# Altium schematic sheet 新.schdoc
size 254 x 209 mm; Symbol: Drawing-Symbol_A4; Company: 嘉立创EDA; Version: V1.0; Page Size: A5; @Project Name: 蜂鸟无人机; @Update Date: 2026-08-29; @Create Date: 2026-08-29; Device: Drawing-Symbol_A4; @Board Name: Board1; @Page Name: P1; @Create Time: 19:18:57; @Page Count: 1; @Page No: 1; @Schematic Name: Schematic1; @Update Time: 19:18:57; @Assembly Variant: Basic; Border: 1; Title Block Position: 3; Size: A4; Width: 1000; Height: 825; Region Start: 1; X Region Count: 6; Y Region Count: 4; Blade Width: 10; Title Block: 1
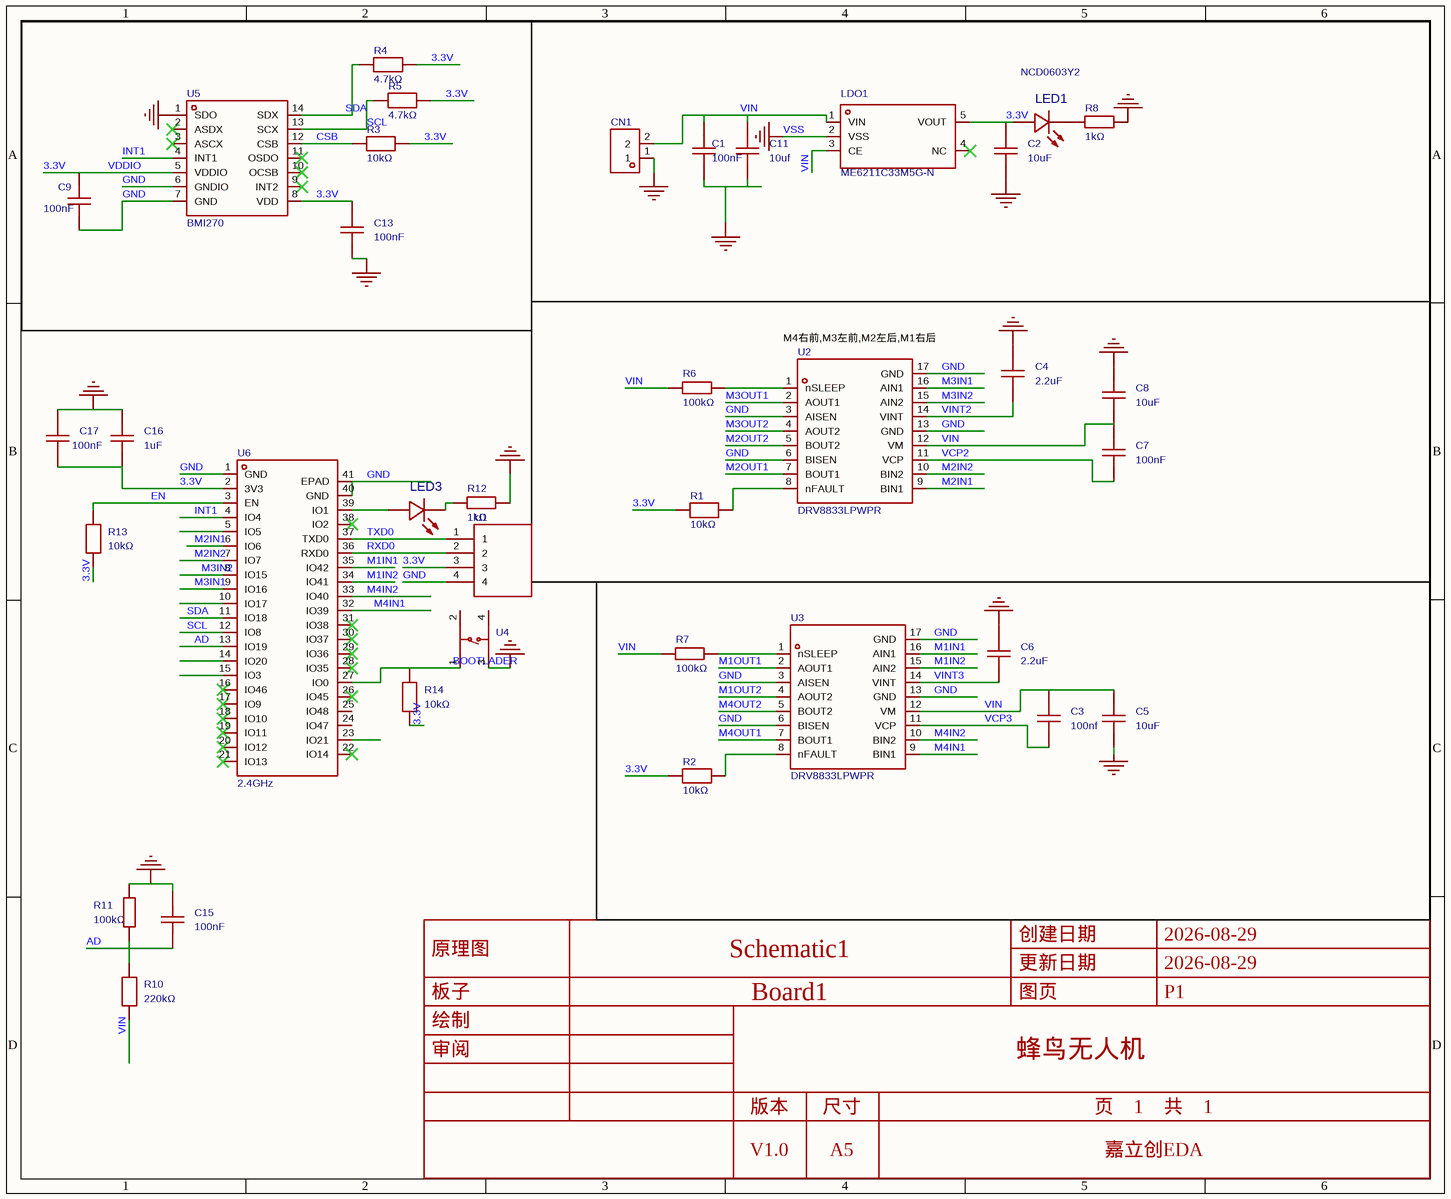
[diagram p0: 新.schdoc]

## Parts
C1  100nF  [C0402]
C2  10uF  [C0402]
C3  100nf  [C0402]
C4  2.2uF  [C0402]
C5  10uF  [C0402]
C6  2.2uF  [C0402]
C7  100nF  [C0402]
C8  10uF  [C0402]
C9  100nF  [C0402]
C11  10uf  [C0402]
C13  100nF  [C0402]
C15  100nF  [C0402]
C16  1uF  [C0402]
C17  100nF  [C0402]
CN1  WAFER-XH254WZ-2AM  [CONN-TH_2P-P2.50_WAFER-XH254WZ-2A]  (value not drawn)
LDO1  ME6211C33M5G-N  [SOT-23-5_L3.0-W1.7-P0.95-LS2.8-BL]
LED1  NCD0603Y2  [LED0603-RD]
LED3  NCD0603Y2  [LED0603-RD]  (value not drawn)
R1  10kΩ  [R0402]
R2  10kΩ  [R0402]
R3  10kΩ  [R0402]
R4  4.7kΩ  [R0402]
R5  4.7kΩ  [R0402]
R6  100kΩ  [R0402]
R7  100kΩ  [R0402]
R8  1kΩ  [R0603]
R10  220kΩ  [R0402]
R11  100kΩ  [R0402]
R12  1kΩ  [R0603]
R13  10kΩ  [R0402]
R14  10kΩ  [R0402]
U1  (no value)  [4p贴片]
U2  DRV8833LPWPR  [ETSSOP-16_L5.0-W4.4-P0.65-LS6.4-BL-EP]
U3  DRV8833LPWPR  [ETSSOP-16_L5.0-W4.4-P0.65-LS6.4-BL-EP]
U4  (no value)  [KEY-SMD_4P-L3.3-W3.3-P2.00-LS4.0]
U5  BMI270  [LGA-14_L3.0-W2.5-P0.50-BR]
U6  2.4GHz  [WIRELM-SMD_ESP32-S3-WROOM-1]

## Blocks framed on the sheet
M4右前,M3左前,M2左后,M1右后: C4 C7 C8 R1 R6 U2

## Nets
GND: C1.1 C2.2 C4.2 C5.1 C6.2 C8.2 C9.2 C11.1 C13.2 C15.1 C16.1 C17.1 CN1.1 LDO1.2(VSS) R8.2 R11.1 R12.2 U1.4 U2.3(AISEN) U2.6(BISEN) U2.13(GND) U2.17(GND) U3.3(AISEN) U3.6(BISEN) U3.13(GND) U3.17(GND) U4.3 U5.1(SDO) U5.6(GNDIO) U5.7(GND) U6.1(GND) U6.40(GND) U6.41(EPAD)  [also labelled VSS]
3.3V: C2.1 C9.1 C13.1 C16.2 C17.2 LDO1.5(VOUT) LED1.2(A) R1.1 R2.1 R3.2 R4.2 R5.2 R13.1 R14.1 U1.3 U5.5(VDDIO) U5.8(VDD) U6.2(3V3)  [also labelled VDDIO]
AD: C15.2 R10.1 R11.2 U6.13(IO19)
BOOTLADER: R14.2 U4.1 U6.27(IO0)
CSB: R3.1 U5.12(CSB)
EN: R13.2 U6.3(EN)
INT1: U5.4(INT1) U6.4(IO4)
M1IN1: U3.16(AIN1) U6.35(IO42)
M1IN2: U3.15(AIN2) U6.34(IO41)
M1OUT1: U3.2(AOUT1)
M1OUT2: U3.4(AOUT2)
M2IN1: U2.9(BIN1) U6.6(IO6)
M2IN2: U2.10(BIN2) U6.7(IO7)
M2OUT1: U2.7(BOUT1)
M2OUT2: U2.5(BOUT2)
M3IN1: U2.16(AIN1) U6.9(IO16)
M3IN2: U2.15(AIN2) U6.8(IO15)
M3OUT1: U2.2(AOUT1)
M3OUT2: U2.4(AOUT2)
M4IN1: U3.9(BIN1) U6.32(IO39)
M4IN2: U3.10(BIN2) U6.33(IO40)
M4OUT1: U3.7(BOUT1)
M4OUT2: U3.5(BOUT2)
RXD0: U1.2 U6.36(RXD0)
SCL: R5.1 U5.13(SCX) U6.12(IO8)
SDA: R4.1 U5.14(SDX) U6.11(IO18)
TXD0: U1.1 U6.37(TXD0)
VCP2: C7.1 U2.11(VCP)
VCP3: C3.1 U3.11(VCP)
VIN: C1.2 C3.2 C5.2 C7.2 C8.1 C11.2 CN1.2 LDO1.1(VIN) LDO1.3(CE) R6.1 R7.1 R10.2 U2.12(VM) U3.12(VM)
VINT2: C4.1 U2.14(VINT)
VINT3: C6.1 U3.14(VINT)
NetLED1_1: LED1.1(K) R8.1
NetLED3_1: LED3.1(K) R12.1
NetLED3_2: LED3.2(A) U6.39(IO1)
NetR1_2: R1.2 U2.8(nFAULT)
NetR2_2: R2.2 U3.8(nFAULT)
NetR6_2: R6.2 U2.1(nSLEEP)
NetR7_2: R7.2 U3.1(nSLEEP)

Not connected (* = marked no-connect by the designer): LDO1 4(NC)*; U4 2 4; U5 2(ASDX)* 3(ASCX)* 9(INT2)* 10(OCSB)* 11(OSDO)*; U6 5(IO5) 10(IO17) 14(IO20) 15(IO3) 16(IO46)* 17(IO9)* 18(IO10)* 19(IO11)* 20(IO12)* 21(IO13)* 22(IO14)* 23(IO21) 24(IO47) 25(IO48) 26(IO45)* 28(IO35)* 29(IO36)* 30(IO37)* 31(IO38)* 38(IO2)*

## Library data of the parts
C1 C11 = CAP_0402: Symbol: Capacitance; ConvertToPcb: yes; ModelId: 36a51122f27c49738f86b3bfa98863e00819f05c4eef4c71ace90d822a990e87; ModelName: C0402_L1.0-W0.5-H0.5; ModelTransform: 39.37,19.685,0,0,0,0,0,0,0
C2 C5 C8 = TCC0402X5R106M6R3ATR: 容值:10uF;精度:±20%;额定电压:6.3V;温度系数:X5R;; Manufacturer: CCTC(三环); Add into BOM: yes; 3D Model: 36a51122f27c49738f86b3bfa98863e0; 3D Model Transform: 39.37,19.685,0,0,0,0,0,0,0; Tolerance: ±20%; Temperature Coefficient: X5R; Voltage Rating: 6.3V; ModelName: C0402_L1.0-W0.5-H0.5
C3 C7 = TCC0402X7R103M500AT: 容值:10nF;精度:±20%;额定电压:50V;温度系数:X7R;; Manufacturer: CCTC(三环); Add into BOM: yes; 3D Model: 36a51122f27c49738f86b3bfa98863e0; 3D Model Transform: 39.37,19.685,0,0,0,0,0,0,0; Tolerance: ±20%; Voltage Rating: 50V; Temperature Coefficient: X7R; ModelName: C0402_L1.0-W0.5-H0.5
C4 C6 = TCC0402X5R225K100AT: 容值:2.2uF;精度:±10%;额定电压:10V;温度系数:X5R;; Manufacturer: CCTC(三环); Add into BOM: yes; 3D Model: 36a51122f27c49738f86b3bfa98863e0; 3D Model Transform: 39.37,19.685,0,0,0,0,0,0,0; Tolerance: ±10%; Voltage Rating: 10V; Temperature Coefficient: X5R; ModelName: C0402_L1.0-W0.5-H0.5
C9 C13 C15 C17 = TCC0402X7R104M160AT: 容值:100nF;精度:±20%;额定电压:16V;温度系数:X7R;; Manufacturer: CCTC(三环); Add into BOM: yes; 3D Model: 36a51122f27c49738f86b3bfa98863e0; 3D Model Transform: 39.37,19.685,0,0,0,0,0,0,0; Tolerance: ±20%; Voltage Rating: 16V; Temperature Coefficient: X7R; ModelName: C0402_L1.0-W0.5-H0.5
C16 = MH0402A105K6R3N5RN: 容值:1uF;精度:±10%;额定电压:6.3V;温度系数:X5R;; Manufacturer: Sunway(信维通信); Add into BOM: yes; 3D Model: 36a51122f27c49738f86b3bfa98863e0; 3D Model Transform: 39.37,19.685,0,0,0,0,0,0,0; Tolerance: ±10%; Voltage Rating: 6.3V; Temperature Coefficient: X5R; ModelName: C0402_L1.0-W0.5-H0.5
CN1 = WAFER-XH254WZ-2AM: 插针结构:1x2P;间距:2.54mm;安装方式:弯插;参考系列:XH;总PIN数:2P;排数:1;每排PIN数:2;额定电流:3A;触头材质:黄铜;工作温度:-25℃~+85℃;; Manufacturer: HANBO(汉博); AddInBom: yes; ModelId: 2585726ed40942d3a71377327c12efd50819f05c4eef4c71ace90d822a990e87; ModelTransform: 295.669,300.7868,0,0,0,0,-0.005,-137.638,-133.858; Pins Structure: 1x2P; Pitch: 2.54mm; Reference Series: XH; Number of PINs Per Row: 2; Current Rating: 3A; Voltage Rating: 250V; Plastic Material: PA66; Flame Retardant Rating: UL94V-0
LDO1 = ME6211C33M5G-N: 输出极性:正极;工作电压:6V;输出电压:3.3V;输出电流:500mA;电源纹波抑制比(PSRR):70dB@(1kHz);输出类型:固定;; Manufacturer: MICRONE(南京微盟); AddInBom: yes; ModelId: 0a2a1b8f50944f73965918ad6e5fe1670819f05c4eef4c71ace90d822a990e87; ModelName: SOT-23-5_L2.9-W1.6-H1.1-LS2.8-P0.95; ModelTransform: 118.60433,114.173,0,90,0,0,0.0005,0.0005,0; Output Configuration: 正极; Voltage - Supply: 6V; Output Voltage: 3.3V; Output Current: 500mA; Voltage Dropout: 120mV@(100mA); standby current: 60uA; Noise: 50uVrms; Output Type: 固定; Number of Outputs: 1
LED1 LED3 = NCD0603Y2: 灯头类型:1.6mmx0.8mm方形灯头;发光颜色:黄色;正向压降(Vf):1.6V~2.6V;功率:65mW;测试电流:25mA;波长:586nm~595nm;二极管配置:独立二极管;透镜颜色:-;色温:-;发光强度:220mcd;发光角度:130°;载带方式:-;工作温度:-30℃~+85℃;; Manufacturer: 国星光电; Symbol: FC-1608YXK-585F08; Convert to PCB: yes; 3D Model: 1f0d29a91be547639d425604e9b96ebb; 3D Model Transform: 63.7794,32.283,0,0,0,0,0,0,0; Illumination Color: 黄色; Power(Watts): 65mW; Test Current: 25mA; Peak Wavelength: 595nm; Diode Configuration: 独立二极管; Luminous Intensity: 220mcd; Viewing Angle: 130°; Half wave width: 15nm
R1-R3 R13 R14 = RCA0210KJLF: 阻值:10kΩ;精度:±5%;功率:62.5mW;; Manufacturer: HKR(香港电阻); Add into BOM: yes; 3D Model: 98c88bc2b9094f218f3a3e30a7012738; 3D Model Transform: 39.37,19.685,0,0,0,0,0,0,0; Tolerance: ±5%; Power(Watts): 62.5mW; ModelName: R0402_L1.0-W0.5-H0.4
R4 R5 = RCA024K7JLF: 电阻类型:厚膜电阻;阻值:4.7kΩ;精度:±5%;功率:62.5mW;工作电压:50V;温度系数:±200ppm/℃;; Manufacturer: HKR(香港电阻); Add into BOM: yes; 3D Model: 98c88bc2b9094f218f3a3e30a7012738; 3D Model Transform: 39.37,19.685,0,0,0,0,0,0,0; Tolerance: ±5%; Power(Watts): 62.5mW; Voltage-Supply(Max): 50V; ModelName: R0402_L1.0-W0.5-H0.4
R6 R7 = RC0402JR-07100KL: 精度:±5%;阻值:100kΩ;功率:1/16W;温度系数:±100ppm/℃;最大工作电压:50V;工作温度范围:-55℃~+155℃;; Manufacturer: YAGEO(国巨); Add into BOM: yes; 3D Model: 671aefced39d4c318694bba8bd8efd39; 3D Model Transform: 39.37,19.685,0,0,0,0,0,0.0005,0; Tolerance: ±5%; Overload Voltage (Max): 50V; Power(Watts): 1/16W; ModelName: R0402_L1.0-W0.5-H0.5
R8 = TR0603B1K00P0525Z: 电阻类型:薄膜电阻;阻值:1kΩ;精度:±0.1%;功率:100mW;温度系数:±25ppm/℃;最大工作电压:75V;工作温度范围:-55℃~+155℃;; Manufacturer: EVER OHMS(天二科技); Symbol: TR0603B1KP0525; Add into BOM: yes; 3D Model: 3281a289d46d4bb1877be1eabd090e13; 3D Model Transform: 62.992,31.496,0,0,0,0,0,0,0; Tolerance: ±0.1%; Overload Voltage (Max): 75V; Power(Watts): 100mW; ModelName: R0603_L1.6-W0.8-H0.8
R10 = FRC0402F2203TS: 电阻类型:厚膜电阻;阻值:220kΩ;精度:±1%;功率:62.5mW;工作电压:50V;温度系数:±100ppm/℃;; Manufacturer: FOJAN(富捷); Add into BOM: yes; 3D Model: 98c88bc2b9094f218f3a3e30a7012738; 3D Model Transform: 39.37,19.685,0,0,0,0,0,0,0; Tolerance: ±1%; Power(Watts): 62.5mW; Voltage-Supply(Max): 50V; ModelName: R0402_L1.0-W0.5-H0.4
R11 = RMC 0402 100K F N: 电阻类型:厚膜电阻;阻值:100kΩ;精度:±1%;功率:62.5mW;工作电压:50V;温度系数:±100ppm/℃;; Manufacturer: Tyohm(幸亚电阻); Symbol: RMC0402100K1%N; Add into BOM: yes; 3D Model: 98c88bc2b9094f218f3a3e30a7012738; 3D Model Transform: 39.37,19.685,0,0,0,0,0,0,0; Tolerance: ±1%; Power(Watts): 62.5mW; Voltage-Supply(Max): 50V; ModelName: R0402_L1.0-W0.5-H0.4
R12 = TR0603B1K00P0525Z: 电阻类型:薄膜电阻;阻值:1kΩ;精度:±0.1%;功率:100mW;温度系数:±25ppm/℃;最大工作电压:75V;工作温度范围:-55℃~+155℃;; Manufacturer: EVER OHMS(天二科技); Symbol: TR0603B1KP0525; Add into BOM: yes; 3D Model: 3281a289d46d4bb1877be1eabd090e13; 3D Model Transform: 62.992,31.496,0,0,0,0,0,0,0; Tolerance: ±0.1%; Power(Watts): 100mW; Overload Voltage (Max): 75V; ModelName: R0603_L1.6-W0.8-H0.8
U1 = 4p贴片: AddInBom: yes
U2 U3 = DRV8833LPWPR: Manufacturer: TI(德州仪器); AddInBom: yes; ModelId: db785e14ad584e05bc67e738b97492ac0819f05c4eef4c71ace90d822a990e87; ModelTransform: 196.85,251.968,0,0,0,0,0,0,0
U4 = TVAF03-N015B2L-R: 按钮形状:圆形按钮;作用力:1.8N;安装方式:立贴;开关长度:3.3mm;开关宽度:3.3mm;开关高度:1.5mm;带支架:不带支架;触点电流:50mA;额定电压:12V;带灯:无;工作寿命:30万次;; Manufacturer: jianfu(键富); AddInBom: yes; ModelId: 350f1a93a7c04f719bf4b3e445b4949f0819f05c4eef4c71ace90d822a990e87; ModelTransform: 157.48,131.8895,0,0,0,0,0,0,0; Actuator Style: 圆形按钮; Operating Force: 1.8N; Switch Height: 1.5mm; with Bracket: 不带支架; Contact Current: 50mA; Voltage Rating: 12V; Actuator/Cap Color: 白色; With Lamp: 无; Life: 30万次
U5 = BMI270: 传感器类型:IMU(加速度计+陀螺仪);接口类型:I2C；SPI;; Manufacturer: Bosch(博世); AddInBom: yes; ModelId: 64f32784a16f466f897e9e56b6bbdf450819f05c4eef4c71ace90d822a990e87; ModelTransform: 118.11,98.425,0,180,0,0,-0.001,0.004,0; Accelerometer Sensing Axis: X,Y,Z; Acceleration Measurement Range (MAX): ±16g; Gyroscope Measurement Range (MAX): ±2000dps; Output Bits: 16bit; Voltage - Supply: 1.71V~3.6V; Cache Size: 2KB; Standby Current: 3.5uA
U6 = ESP32-S3-WROOM-1-N4R2: 核心芯片:ESP32-S3;频率:2.4GHz;天线形式:板载PCB天线;发射功率:20.5dBm;接收灵敏度:-103.5dBm;; Manufacturer: ESPRESSIF(乐鑫); AddInBom: yes; ModelId: 481f5bdfc076422c9bb3c23c3ada9c170819f05c4eef4c71ace90d822a990e87; ModelTransform: 708.73866,1003.97437,0,0,0,0,0,143.7,0; Wireless Standard: Bluetooth5.0; Interface Type: I2C；GPIO；UART；SPI；USB；I2S; Voltage - Supply: 3V~3.6V; Receive  Current: 95mA; Send  Current: 355mA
